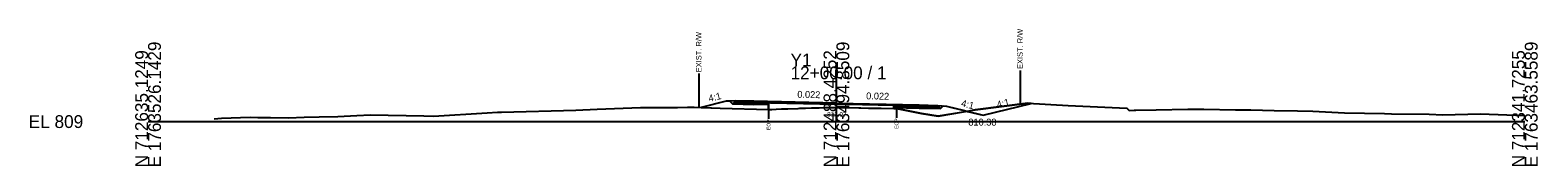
# Model space of a CAD drawing. Extents: x -26 to 1303, y -10 to 9524.
# Drawn here: x -25.7 to 302.8, y 1990.3 to 2020 of the extents above; entities that cross this region are included whole.
import ezdxf

# ---------------------------------------------------------------- set-up
doc = ezdxf.new("R2010")
doc.units = 0
for name, color, linetype in [('Default', 7, 'Continuous'), ('Exist CMT Pavement', 7, 'Continuous'), ('Exist Cross Section Cell', 7, 'Continuous'), ('Exist XS Center Line Elevation Label', 7, 'Continuous'), ('Exist XS Ground Line', 7, 'Continuous'), ('Old_Level_10', 7, 'Continuous'), ('Prop CMT Pvmt Course 1', 7, 'Continuous'), ('Prop CMT Pvmt Course 3', 7, 'Continuous'), ('Prop CMT Pvmt Surface', 7, 'Continuous'), ('Prop CMT Pvmt Surface Shoulder', 7, 'Continuous'), ('Prop CMT Shld Paved Course 1', 7, 'Continuous'), ('Prop CMT Shld Paved Course 3', 7, 'Continuous'), ('Prop CMT Slope Grass', 7, 'Continuous'), ('Prop CMT Subgrade Earthwork', 7, 'Continuous'), ('Prop XS Ditch Standard Text', 7, 'Continuous'), ('Prop XS Earthwork Shape', 7, 'Continuous'), ('Prop XS SE Text', 7, 'Continuous'), ('Prop XS Side Slope Text', 7, 'Continuous'), ('Prop XS Wedging', 7, 'Continuous')]:
    doc.layers.add(name, color=color, linetype=linetype)

msp = doc.modelspace()

# ---------------------------------------------------------------- linework, layer by layer
at = {"layer": 'Exist CMT Pavement'}
msp.add_lwpolyline([(135.22, 2002.62), (135.93, 2002.67), (136.89, 2002.72), (138.01, 2002.76), (139.44, 2002.8), (141.65, 2002.89), (142, 2002.9), (143.29, 2002.95), (144.56, 2003), (146.26, 2003.03), (147.17, 2003.05), (147.48, 2003.06), (148.86, 2003.06), (149.67, 2003.07), (150, 2003.07), (151.4, 2003.06), (152.22, 2003.06), (154.87, 2003.02), (155.28, 2003.01), (156.97, 2002.97), (157.34, 2002.96), (159.76, 2002.94), (162.48, 2002.89)], dxfattribs=at)
at = {"layer": 'Exist Cross Section Cell'}
for p, q in [((150, 2000), (150, 2012.06)), ((0, 2000), (150, 2000)), ((150, 2000), (300, 2000))]:
    msp.add_line(p, q, dxfattribs=at)
at = {"layer": 'Exist XS Ground Line'}
msp.add_lwpolyline([(14.4, 2000.62), (15.97, 2000.78), (22.22, 2000.95), (23.91, 2000.93), (26.66, 2000.86), (30.57, 2000.82), (34.05, 2000.96), (37.25, 2001.03), (41.34, 2001.12), (45.5, 2001.33), (48.44, 2001.46), (60.06, 2001.23), (62.21, 2001.21), (73.9, 2001.9), (76.11, 2002.03), (76.65, 2002.06), (77.01, 2002.06), (93.2, 2002.48), (97.86, 2002.71), (107.33, 2003.08), (115.34, 2003.11), (117.55, 2003.12), (118.99, 2003.12), (124.64, 2002.94), (135.22, 2002.62), (135.93, 2002.67), (136.89, 2002.72), (138.01, 2002.76), (139.44, 2002.8), (141.65, 2002.89), (142, 2002.9), (143.29, 2002.95), (144.56, 2003), (146.26, 2003.03), (147.17, 2003.05), (147.48, 2003.06), (148.86, 2003.06), (149.67, 2003.07), (150, 2003.07), (151.4, 2003.06), (152.22, 2003.06), (154.87, 2003.02), (155.28, 2003.01), (156.97, 2002.97), (157.34, 2002.96), (159.76, 2002.94), (162.48, 2002.89), (163.08, 2002.86), (168.55, 2001.79), (172.19, 2001.15), (180.24, 2002.54), (191.73, 2004.02), (200.46, 2003.53), (213.27, 2002.94), (213.77, 2002.44), (214.91, 2002.5), (215.27, 2002.52), (219.65, 2002.56), (226.58, 2002.72), (230.04, 2002.75), (236.98, 2002.6), (240.27, 2002.56), (245.41, 2002.45), (250.49, 2002.34), (253.84, 2002.27), (260.72, 2001.89), (269.45, 2001.75), (270.96, 2001.73), (279.13, 2001.59), (282.14, 2001.51), (290.29, 2001.67), (300, 2001.3)], dxfattribs=at)
at = {"layer": 'Old_Level_10'}
for p, q in [((190, 2011.2), (190, 2003.8)), ((120, 2010.48), (120, 2003.08)), ((135.22, 2002.62), (135.22, 2000.57)), ((163.08, 2002.86), (163.08, 2000.81))]:
    msp.add_line(p, q, dxfattribs=at)
at = {"layer": 'Prop CMT Pvmt Course 1'}
for points in [[(132, 2004.18), (129.93, 2004.22)], [(129.93, 2004.22), (129.93, 2004.22)], [(150, 2004.03), (132, 2004.43)], [(132, 2004.43), (132, 2004.18)], [(132, 2004.18), (150, 2003.78)], [(150, 2003.78), (150, 2004.03)], [(150, 2004.03), (168, 2003.63)], [(150, 2003.78), (150, 2003.78), (150, 2003.78)], [(162.48, 2003.5), (150, 2003.78)], [(168, 2003.38), (162.48, 2003.5)], [(162.48, 2003.5), (162.48, 2003.5)], [(168, 2003.63), (168, 2003.38)]]:
    msp.add_lwpolyline(points, dxfattribs=at)
at = {"layer": 'Prop CMT Pvmt Course 3'}
for points in [[(129.93, 2004.22), (132, 2004.18)], [(129.93, 2003.8), (129.93, 2004.22)], [(132, 2004.18), (132, 2003.76)], [(135.22, 2004.1), (135.22, 2003.69)], [(132, 2003.76), (129.93, 2003.8)], [(162.48, 2003.5), (168, 2003.38)], [(162.48, 2003.08), (162.48, 2003.5)], [(168, 2002.96), (162.48, 2003.08)], [(168, 2003.38), (168, 2002.96)]]:
    msp.add_lwpolyline(points, dxfattribs=at)
at = {"layer": 'Prop CMT Pvmt Surface'}
for points in [[(150, 2004.03), (132, 2004.43)], [(150, 2004.03), (168, 2003.63)]]:
    msp.add_lwpolyline(points, dxfattribs=at)
at = {"layer": 'Prop CMT Pvmt Surface Shoulder'}
for points in [[(132, 2004.43), (128, 2004.51)], [(168, 2003.63), (172, 2003.54)]]:
    msp.add_lwpolyline(points, dxfattribs=at)
at = {"layer": 'Prop CMT Shld Paved Course 1'}
for points in [[(132, 2004.43), (128, 2004.51), (127.76, 2004.27)], [(127.76, 2004.27), (132, 2004.18)], [(132, 2004.18), (132, 2004.43)], [(168, 2003.63), (172, 2003.54), (172.26, 2003.28)], [(168, 2003.38), (168, 2003.63)], [(172.26, 2003.28), (168, 2003.38)]]:
    msp.add_lwpolyline(points, dxfattribs=at)
at = {"layer": 'Prop CMT Shld Paved Course 3'}
for points in [[(127.76, 2004.27), (127.35, 2003.86)], [(132, 2004.18), (127.76, 2004.27)], [(132, 2003.84), (132, 2004.18)], [(127.35, 2003.86), (132, 2003.76)], [(168, 2003.38), (172.26, 2003.28)], [(168, 2003.05), (168, 2003.38)], [(172.68, 2002.86), (168, 2002.96)], [(172.26, 2003.28), (172.68, 2002.86)]]:
    msp.add_lwpolyline(points, dxfattribs=at)
at = {"layer": 'Prop CMT Slope Grass'}
for points in [[(128, 2004.51), (126, 2004.44), (120.51, 2003.07)], [(172, 2003.54), (174, 2003.38), (182, 2001.38), (192.4, 2003.98)], [(172, 2003.54), (174, 2003.38), (177.9, 2002.41)]]:
    msp.add_lwpolyline(points, dxfattribs=at)
at = {"layer": 'Prop CMT Subgrade Earthwork'}
for p, q in [((132, 2003.76), (127.35, 2003.86)), ((135.22, 2003.69), (132, 2003.76)), ((135.22, 2003.69), (135.22, 2002.62)), ((162.48, 2002.89), (162.48, 2003.08)), ((162.48, 2003.08), (168, 2002.96)), ((168, 2002.96), (172.68, 2002.86))]:
    msp.add_line(p, q, dxfattribs=at)
for points in [[(126.74, 2004.47), (127.35, 2003.86)], [(173.26, 2003.44), (172.68, 2002.86)]]:
    msp.add_lwpolyline(points, dxfattribs=at)
at = {"layer": 'Prop XS Earthwork Shape'}
for points in [[(135.22, 2003.69), (132, 2003.76), (127.35, 2003.86), (126.74, 2004.47), (126, 2004.44), (120.51, 2003.07), (124.64, 2002.94), (135.22, 2002.62)], [(174, 2003.38), (177.9, 2002.41), (178.54, 2002.24), (172.19, 2001.15), (168.55, 2001.79), (163.08, 2002.86), (162.48, 2002.89), (162.48, 2003.08), (168, 2002.96), (172.68, 2002.86), (173.26, 2003.44)], [(182, 2001.38), (192.4, 2003.98), (191.73, 2004.02), (180.24, 2002.54), (178.54, 2002.24)]]:
    msp.add_lwpolyline(points, close=True, dxfattribs=at)
at = {"layer": 'Prop XS Wedging'}
for p, q in [((135.22, 2003.77), (135.22, 2003.44)), ((135.22, 2003.44), (135.22, 2002.62)), ((135.22, 2002.62), (135.93, 2002.67)), ((135.93, 2002.67), (136.89, 2002.72)), ((136.89, 2002.72), (138.01, 2002.76)), ((142, 2002.9), (143.29, 2002.95)), ((143.29, 2002.95), (144.56, 2003)), ((148.86, 2003.06), (149.67, 2003.07)), ((149.67, 2003.07), (150, 2003.07)), ((152.22, 2003.06), (154.87, 2003.02)), ((154.87, 2003.02), (155.28, 2003.01)), ((157.34, 2002.96), (159.76, 2002.94)), ((159.76, 2002.94), (162.48, 2002.89)), ((162.48, 2002.89), (162.48, 2003.17))]:
    msp.add_line(p, q, dxfattribs=at)
for points in [[(162.48, 2003.17), (162.48, 2003.5), (135.22, 2004.1), (135.22, 2003.77)], [(138.01, 2002.76), (139.44, 2002.8), (141.65, 2002.89), (142, 2002.9)], [(144.56, 2003), (146.26, 2003.03), (147.17, 2003.05)], [(147.17, 2003.05), (147.48, 2003.06), (148.86, 2003.06)], [(150, 2003.07), (151.4, 2003.06), (152.22, 2003.06)], [(155.28, 2003.01), (156.97, 2002.97), (157.34, 2002.96)]]:
    msp.add_lwpolyline(points, dxfattribs=at)

# ---------------------------------------------------------------- texts
at = {"layer": 'Default'}
msp.add_text('-', height=0.0001, dxfattribs=at).set_placement((0, 2000))
at = {"layer": 'Exist Cross Section Cell'}
for s, p in [('E 1763526.1429', (2.8, 1990)), ('E 1763494.8509', (152.8, 1990)), ('E 1763463.5589', (302.8, 1990)), ('N 712635.1249', (0, 1990)), ('N 712488.4252', (150, 1990)), ('N 712341.7255', (300, 1990))]:
    msp.add_text(s, height=2.8, rotation=90, dxfattribs=at).set_placement(p)
for s, p in [('Y1', (140, 2012.06)), ('12+00.00 / 1', (140, 2009.26)), ('EL 809', (-26, 1998.6))]:
    msp.add_text(s, height=2.8, dxfattribs=at).set_placement(p)
at = {"layer": 'Exist XS Center Line Elevation Label'}
msp.add_text('812.07', height=1, dxfattribs=at).set_placement((147.97, 2001.07))
at = {"layer": 'Old_Level_10'}
for s, height, p in [('EXIST. R/W', 1.181, (120.59, 2010.79)), ('EXIST. R/W', 1.181, (190.59, 2011.5)), ('EOP', 0.787, (135.61, 1998.17)), ('EOP', 0.787, (163.48, 1998.41))]:
    msp.add_text(s, height=height, rotation=90, dxfattribs=at).set_placement(p)
at = {"layer": 'Prop XS Ditch Standard Text'}
msp.add_text('810.38', height=1.5, dxfattribs=at).set_placement((178.74, 1999.13))
at = {"layer": 'Prop XS SE Text'}
for p in [(141.46, 2005.22), (156.46, 2004.88)]:
    msp.add_text('0.022', height=1.5, rotation=358.7318, dxfattribs=at).set_placement(p)
at = {"layer": 'Prop XS Side Slope Text'}
for rotation, p in [(14.0362, (122.31, 2004.29)), (345.9638, (177.06, 2003.36)), (14.0363, (185.13, 2002.94))]:
    msp.add_text('4:1', height=1.5, rotation=rotation, dxfattribs=at).set_placement(p)

doc.saveas('drawing.dxf')
